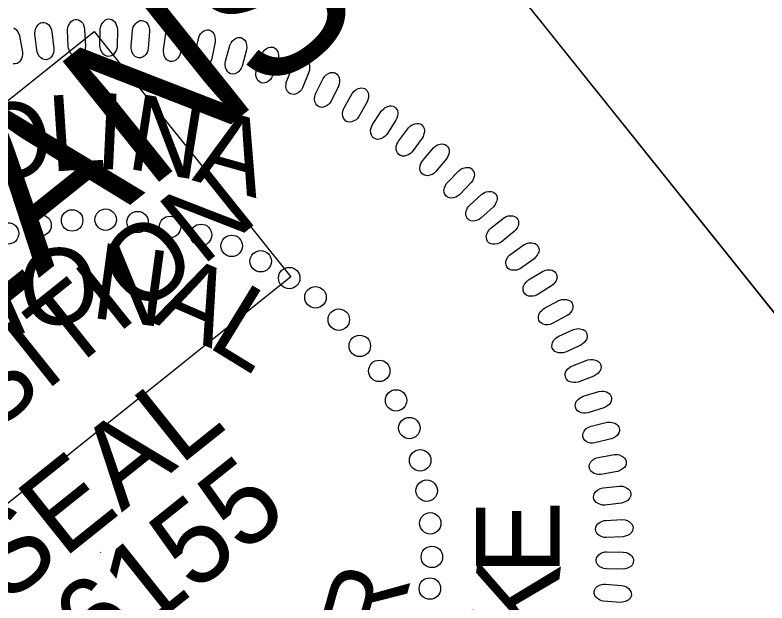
# Model space of a CAD drawing. Extents: x 473546 to 475544, y 505920 to 507827.
# Drawn here: x 474878.2 to 474934.4, y 507684.5 to 507728.4 of the extents above; entities that cross this region are included whole.
import ezdxf

# ---------------------------------------------------------------- set-up
doc = ezdxf.new("R2010")
doc.units = 0
for name, color, linetype in [('Sheet Plan CELL', 7, 'Continuous'), ('Sheet Profile Grid Minor CELL', 7, 'Continuous'), ('Sheet Sticker Incomplete CELL', 7, 'Continuous')]:
    doc.layers.add(name, color=color, linetype=linetype)

msp = doc.modelspace()

# ---------------------------------------------------------------- linework, layer by layer
at = {"layer": 'Sheet Plan CELL'}
for points in [[(474860.894, 507798.628), (473689.748, 506861.329), (474345.841, 506041.547), (475516.967, 506978.831)], [(474806.271, 507706.801), (474884.328, 507769.288), (474954.641, 507681.452), (474876.574, 507618.957)]]:
    msp.add_lwpolyline(points, close=True, dxfattribs=at)
at = {"layer": 'Sheet Profile Grid Minor CELL'}
msp.add_line((474884.563, 507688.269), (474884.592, 507688.232), dxfattribs=at)
for points in [[(474879.828, 507725.763), (474879.694, 507726.982), (474879.707, 507727.205), (474879.744, 507727.349), (474879.837, 507727.53), (474879.922, 507727.65), (474880.025, 507727.741), (474880.124, 507727.792), (474880.234, 507727.824), (474880.347, 507727.817), (474880.469, 507727.799), (474880.58, 507727.752), (474880.695, 507727.664), (474880.763, 507727.591), (474880.847, 507727.45), (474880.925, 507727.278), (474880.965, 507727.122), (474881.109, 507725.873), (474881.105, 507725.702), (474881.076, 507725.559), (474881.004, 507725.39), (474880.908, 507725.24), (474880.82, 507725.149), (474880.67, 507725.072), (474880.524, 507725.037), (474880.372, 507725.06), (474880.262, 507725.099), (474880.124, 507725.183), (474879.987, 507725.339), (474879.901, 507725.51), (474879.857, 507725.636)], [(474882.185, 507726.019), (474882.128, 507727.244), (474882.155, 507727.465), (474882.201, 507727.607), (474882.305, 507727.782), (474882.397, 507727.895), (474882.505, 507727.98), (474882.608, 507728.025), (474882.719, 507728.051), (474882.832, 507728.036), (474882.953, 507728.011), (474883.06, 507727.956), (474883.169, 507727.862), (474883.233, 507727.785), (474883.307, 507727.638), (474883.375, 507727.462), (474883.405, 507727.303), (474883.47, 507726.048), (474883.455, 507725.878), (474883.417, 507725.736), (474883.336, 507725.573), (474883.23, 507725.428), (474883.136, 507725.344), (474882.982, 507725.277), (474882.834, 507725.25), (474882.683, 507725.283), (474882.576, 507725.328), (474882.444, 507725.422), (474882.317, 507725.586), (474882.241, 507725.762), (474882.206, 507725.89)], [(474884.549, 507726.097), (474884.569, 507727.323), (474884.61, 507727.542), (474884.664, 507727.681), (474884.779, 507727.849), (474884.878, 507727.957), (474884.992, 507728.034), (474885.097, 507728.073), (474885.21, 507728.09), (474885.321, 507728.069), (474885.441, 507728.037), (474885.544, 507727.976), (474885.647, 507727.874), (474885.706, 507727.793), (474885.77, 507727.642), (474885.827, 507727.462), (474885.847, 507727.302), (474885.834, 507726.046), (474885.809, 507725.876), (474885.761, 507725.737), (474885.669, 507725.58), (474885.555, 507725.441), (474885.456, 507725.363), (474885.298, 507725.306), (474885.148, 507725.289), (474884.999, 507725.331), (474884.896, 507725.383), (474884.771, 507725.485), (474884.654, 507725.656), (474884.589, 507725.837), (474884.562, 507725.967)], [(474886.878, 507726.021), (474886.975, 507727.245), (474887.03, 507727.46), (474887.093, 507727.596), (474887.218, 507727.756), (474887.324, 507727.857), (474887.442, 507727.928), (474887.549, 507727.96), (474887.663, 507727.97), (474887.773, 507727.942), (474887.89, 507727.902), (474887.989, 507727.835), (474888.086, 507727.727), (474888.14, 507727.642), (474888.194, 507727.488), (474888.24, 507727.304), (474888.25, 507727.144), (474888.157, 507725.89), (474888.121, 507725.723), (474888.066, 507725.587), (474887.963, 507725.436), (474887.841, 507725.305), (474887.737, 507725.233), (474887.576, 507725.186), (474887.426, 507725.178), (474887.28, 507725.23), (474887.18, 507725.288), (474887.061, 507725.397), (474886.955, 507725.576), (474886.902, 507725.76), (474886.883, 507725.891)], [(474889.298, 507725.79), (474889.472, 507727.004), (474889.54, 507727.215), (474889.612, 507727.347), (474889.746, 507727.498), (474889.858, 507727.593), (474889.98, 507727.656), (474890.09, 507727.681), (474890.204, 507727.685), (474890.312, 507727.649), (474890.426, 507727.603), (474890.521, 507727.529), (474890.611, 507727.415), (474890.658, 507727.327), (474890.704, 507727.17), (474890.738, 507726.984), (474890.738, 507726.823), (474890.566, 507725.578), (474890.52, 507725.413), (474890.456, 507725.281), (474890.345, 507725.136), (474890.214, 507725.014), (474890.106, 507724.948), (474889.943, 507724.911), (474889.791, 507724.913), (474889.649, 507724.973), (474889.553, 507725.038), (474889.441, 507725.154), (474889.347, 507725.339), (474889.306, 507725.527), (474889.295, 507725.659)], [(474891.648, 507725.433), (474891.897, 507726.634), (474891.979, 507726.842), (474892.059, 507726.968), (474892.203, 507727.111), (474892.321, 507727.199), (474892.446, 507727.254), (474892.557, 507727.271), (474892.671, 507727.269), (474892.777, 507727.226), (474892.888, 507727.172), (474892.978, 507727.092), (474893.06, 507726.973), (474893.102, 507726.883), (474893.138, 507726.722), (474893.159, 507726.535), (474893.149, 507726.374), (474892.9, 507725.142), (474892.844, 507724.981), (474892.772, 507724.853), (474892.651, 507724.716), (474892.513, 507724.601), (474892.402, 507724.543), (474892.236, 507724.516), (474892.085, 507724.528), (474891.948, 507724.597), (474891.855, 507724.667), (474891.751, 507724.79), (474891.668, 507724.981), (474891.639, 507725.171), (474891.636, 507725.303)], [(474893.926, 507724.923), (474894.252, 507726.106), (474894.346, 507726.307), (474894.433, 507726.428), (474894.586, 507726.563), (474894.709, 507726.642), (474894.838, 507726.689), (474894.949, 507726.7), (474895.063, 507726.69), (474895.166, 507726.641), (474895.273, 507726.58), (474895.358, 507726.495), (474895.432, 507726.371), (474895.469, 507726.278), (474895.494, 507726.116), (474895.505, 507725.927), (474895.484, 507725.768), (474895.159, 507724.554), (474895.092, 507724.397), (474895.012, 507724.273), (474894.883, 507724.144), (474894.738, 507724.038), (474894.623, 507723.987), (474894.456, 507723.971), (474894.306, 507723.991), (474894.173, 507724.069), (474894.086, 507724.145), (474893.989, 507724.275), (474893.919, 507724.47), (474893.901, 507724.661), (474893.907, 507724.794)], [(474896.236, 507724.279), (474896.634, 507725.439), (474896.741, 507725.635), (474896.836, 507725.75), (474896.997, 507725.874), (474897.125, 507725.946), (474897.256, 507725.985), (474897.368, 507725.989), (474897.481, 507725.971), (474897.58, 507725.916), (474897.684, 507725.848), (474897.763, 507725.758), (474897.83, 507725.629), (474897.861, 507725.535), (474897.876, 507725.371), (474897.874, 507725.182), (474897.843, 507725.024), (474897.443, 507723.833), (474897.366, 507723.68), (474897.278, 507723.563), (474897.142, 507723.441), (474896.99, 507723.345), (474896.872, 507723.301), (474896.705, 507723.295), (474896.557, 507723.325), (474896.429, 507723.411), (474896.346, 507723.493), (474896.257, 507723.629), (474896.199, 507723.827), (474896.194, 507724.019), (474896.208, 507724.152)], [(474898.502, 507723.466), (474898.972, 507724.599), (474899.091, 507724.787), (474899.192, 507724.896), (474899.36, 507725.01), (474899.492, 507725.074), (474899.627, 507725.105), (474899.739, 507725.101), (474899.85, 507725.077), (474899.946, 507725.015), (474900.045, 507724.942), (474900.119, 507724.847), (474900.177, 507724.714), (474900.202, 507724.618), (474900.206, 507724.454), (474900.193, 507724.265), (474900.152, 507724.109), (474899.677, 507722.946), (474899.592, 507722.798), (474899.496, 507722.686), (474899.352, 507722.573), (474899.196, 507722.487), (474899.075, 507722.45), (474898.907, 507722.455), (474898.762, 507722.494), (474898.639, 507722.588), (474898.561, 507722.675), (474898.482, 507722.816), (474898.437, 507723.018), (474898.444, 507723.21), (474898.466, 507723.341)], [(474900.668, 507722.532), (474901.208, 507723.633), (474901.338, 507723.813), (474901.446, 507723.916), (474901.622, 507724.019), (474901.758, 507724.074), (474901.894, 507724.097), (474902.005, 507724.086), (474902.115, 507724.055), (474902.207, 507723.987), (474902.301, 507723.907), (474902.368, 507723.808), (474902.418, 507723.672), (474902.437, 507723.574), (474902.431, 507723.41), (474902.405, 507723.223), (474902.355, 507723.07), (474901.808, 507721.938), (474901.713, 507721.796), (474901.612, 507721.69), (474901.461, 507721.587), (474901.299, 507721.511), (474901.177, 507721.482), (474901.009, 507721.498), (474900.866, 507721.546), (474900.75, 507721.647), (474900.678, 507721.738), (474900.607, 507721.884), (474900.575, 507722.089), (474900.593, 507722.28), (474900.624, 507722.409)], [(474902.783, 507721.456), (474903.391, 507722.522), (474903.533, 507722.693), (474903.647, 507722.789), (474903.828, 507722.881), (474903.968, 507722.927), (474904.105, 507722.941), (474904.215, 507722.924), (474904.323, 507722.885), (474904.41, 507722.812), (474904.499, 507722.727), (474904.56, 507722.624), (474904.601, 507722.484), (474904.614, 507722.386), (474904.598, 507722.222), (474904.561, 507722.037), (474904.501, 507721.888), (474903.884, 507720.793), (474903.781, 507720.657), (474903.672, 507720.558), (474903.515, 507720.464), (474903.349, 507720.398), (474903.224, 507720.377), (474903.058, 507720.403), (474902.919, 507720.46), (474902.809, 507720.569), (474902.743, 507720.664), (474902.682, 507720.813), (474902.663, 507721.02), (474902.693, 507721.209), (474902.732, 507721.337)], [(474904.911, 507720.196), (474905.586, 507721.221), (474905.738, 507721.383), (474905.858, 507721.472), (474906.045, 507721.551), (474906.186, 507721.59), (474906.324, 507721.595), (474906.433, 507721.571), (474906.538, 507721.525), (474906.62, 507721.447), (474906.704, 507721.356), (474906.758, 507721.249), (474906.791, 507721.108), (474906.798, 507721.009), (474906.771, 507720.846), (474906.723, 507720.664), (474906.654, 507720.518), (474905.969, 507719.464), (474905.857, 507719.335), (474905.742, 507719.243), (474905.58, 507719.159), (474905.41, 507719.104), (474905.285, 507719.091), (474905.12, 507719.127), (474904.985, 507719.193), (474904.882, 507719.308), (474904.822, 507719.407), (474904.77, 507719.561), (474904.764, 507719.767), (474904.806, 507719.955), (474904.852, 507720.08)], [(474906.851, 507718.965), (474907.588, 507719.945), (474907.749, 507720.097), (474907.875, 507720.178), (474908.067, 507720.247), (474908.211, 507720.276), (474908.348, 507720.272), (474908.456, 507720.241), (474908.557, 507720.189), (474908.635, 507720.106), (474908.713, 507720.01), (474908.76, 507719.9), (474908.784, 507719.757), (474908.784, 507719.657), (474908.747, 507719.497), (474908.687, 507719.317), (474908.61, 507719.177), (474907.86, 507718.168), (474907.74, 507718.046), (474907.62, 507717.961), (474907.453, 507717.888), (474907.28, 507717.843), (474907.154, 507717.838), (474906.993, 507717.885), (474906.861, 507717.959), (474906.766, 507718.081), (474906.712, 507718.183), (474906.67, 507718.339), (474906.676, 507718.546), (474906.731, 507718.73), (474906.785, 507718.852)], [(474908.657, 507717.523), (474909.455, 507718.455), (474909.626, 507718.597), (474909.756, 507718.67), (474909.952, 507718.726), (474910.096, 507718.746), (474910.234, 507718.734), (474910.339, 507718.696), (474910.438, 507718.638), (474910.509, 507718.55), (474910.581, 507718.449), (474910.621, 507718.336), (474910.636, 507718.193), (474910.63, 507718.093), (474910.584, 507717.935), (474910.512, 507717.76), (474910.426, 507717.624), (474909.615, 507716.664), (474909.487, 507716.55), (474909.362, 507716.474), (474909.191, 507716.411), (474909.015, 507716.378), (474908.889, 507716.38), (474908.73, 507716.436), (474908.604, 507716.519), (474908.517, 507716.646), (474908.469, 507716.752), (474908.437, 507716.91), (474908.457, 507717.117), (474908.523, 507717.298), (474908.584, 507717.415)], [(474910.492, 507715.868), (474911.347, 507716.747), (474911.526, 507716.879), (474911.661, 507716.943), (474911.86, 507716.987), (474912.006, 507716.998), (474912.142, 507716.977), (474912.245, 507716.933), (474912.338, 507716.869), (474912.405, 507716.776), (474912.47, 507716.671), (474912.504, 507716.556), (474912.509, 507716.411), (474912.497, 507716.313), (474912.441, 507716.158), (474912.359, 507715.987), (474912.264, 507715.857), (474911.394, 507714.95), (474911.259, 507714.845), (474911.13, 507714.776), (474910.955, 507714.724), (474910.777, 507714.702), (474910.652, 507714.712), (474910.497, 507714.778), (474910.376, 507714.869), (474910.297, 507715.001), (474910.257, 507715.11), (474910.235, 507715.27), (474910.267, 507715.475), (474910.344, 507715.65), (474910.413, 507715.764)], [(474912.16, 507714.174), (474913.068, 507714.998), (474913.256, 507715.117), (474913.394, 507715.173), (474913.595, 507715.204), (474913.741, 507715.206), (474913.876, 507715.176), (474913.975, 507715.126), (474914.066, 507715.056), (474914.126, 507714.96), (474914.185, 507714.851), (474914.211, 507714.734), (474914.207, 507714.589), (474914.188, 507714.491), (474914.123, 507714.341), (474914.03, 507714.175), (474913.928, 507714.052), (474913.002, 507713.201), (474912.862, 507713.104), (474912.728, 507713.044), (474912.55, 507713.003), (474912.371, 507712.992), (474912.247, 507713.01), (474912.097, 507713.086), (474911.981, 507713.183), (474911.911, 507713.321), (474911.877, 507713.432), (474911.865, 507713.593), (474911.91, 507713.795), (474911.998, 507713.966), (474912.074, 507714.075)], [(474913.732, 507712.447), (474914.691, 507713.214), (474914.885, 507713.321), (474915.027, 507713.368), (474915.23, 507713.386), (474915.376, 507713.379), (474915.508, 507713.341), (474915.604, 507713.284), (474915.69, 507713.209), (474915.745, 507713.109), (474915.796, 507712.997), (474915.814, 507712.878), (474915.802, 507712.734), (474915.777, 507712.637), (474915.702, 507712.491), (474915.599, 507712.332), (474915.489, 507712.215), (474914.512, 507711.424), (474914.366, 507711.336), (474914.228, 507711.284), (474914.048, 507711.254), (474913.869, 507711.255), (474913.746, 507711.281), (474913.601, 507711.366), (474913.492, 507711.47), (474913.43, 507711.612), (474913.404, 507711.725), (474913.402, 507711.886), (474913.46, 507712.086), (474913.558, 507712.25), (474913.64, 507712.355)], [(474915.232, 507710.521), (474916.236, 507711.226), (474916.436, 507711.32), (474916.581, 507711.358), (474916.785, 507711.364), (474916.931, 507711.348), (474917.06, 507711.302), (474917.152, 507711.239), (474917.233, 507711.158), (474917.281, 507711.055), (474917.325, 507710.94), (474917.337, 507710.82), (474917.315, 507710.677), (474917.284, 507710.583), (474917.2, 507710.441), (474917.087, 507710.289), (474916.97, 507710.179), (474915.945, 507709.451), (474915.794, 507709.373), (474915.653, 507709.329), (474915.472, 507709.311), (474915.293, 507709.323), (474915.172, 507709.356), (474915.032, 507709.45), (474914.93, 507709.562), (474914.877, 507709.707), (474914.858, 507709.821), (474914.867, 507709.982), (474914.937, 507710.177), (474915.045, 507710.336), (474915.134, 507710.434)], [(474916.563, 507708.59), (474917.61, 507709.23), (474917.817, 507709.313), (474917.963, 507709.341), (474918.167, 507709.335), (474918.311, 507709.309), (474918.437, 507709.254), (474918.526, 507709.186), (474918.601, 507709.1), (474918.643, 507708.995), (474918.68, 507708.877), (474918.683, 507708.757), (474918.653, 507708.615), (474918.616, 507708.523), (474918.523, 507708.387), (474918.402, 507708.243), (474918.277, 507708.14), (474917.209, 507707.478), (474917.052, 507707.408), (474916.91, 507707.374), (474916.727, 507707.367), (474916.55, 507707.39), (474916.431, 507707.431), (474916.298, 507707.534), (474916.203, 507707.651), (474916.159, 507707.8), (474916.147, 507707.915), (474916.165, 507708.075), (474916.248, 507708.265), (474916.366, 507708.417), (474916.461, 507708.51)], [(474917.745, 507706.479), (474918.83, 507707.051), (474919.041, 507707.121), (474919.189, 507707.141), (474919.392, 507707.12), (474919.534, 507707.085), (474919.657, 507707.024), (474919.741, 507706.95), (474919.811, 507706.86), (474919.846, 507706.752), (474919.875, 507706.632), (474919.871, 507706.511), (474919.831, 507706.372), (474919.789, 507706.282), (474919.689, 507706.153), (474919.558, 507706.016), (474919.428, 507705.922), (474918.32, 507705.328), (474918.159, 507705.268), (474918.015, 507705.243), (474917.832, 507705.248), (474917.656, 507705.282), (474917.54, 507705.33), (474917.414, 507705.441), (474917.326, 507705.564), (474917.292, 507705.715), (474917.287, 507705.831), (474917.315, 507705.989), (474917.41, 507706.174), (474917.537, 507706.318), (474917.638, 507706.404)], [(474918.806, 507704.383), (474919.925, 507704.887), (474920.14, 507704.942), (474920.289, 507704.953), (474920.49, 507704.92), (474920.629, 507704.876), (474920.749, 507704.806), (474920.827, 507704.728), (474920.892, 507704.633), (474920.92, 507704.524), (474920.942, 507704.402), (474920.93, 507704.282), (474920.882, 507704.146), (474920.834, 507704.058), (474920.725, 507703.935), (474920.586, 507703.807), (474920.45, 507703.721), (474919.307, 507703.198), (474919.143, 507703.149), (474918.997, 507703.133), (474918.816, 507703.149), (474918.642, 507703.194), (474918.53, 507703.249), (474918.41, 507703.368), (474918.331, 507703.496), (474918.306, 507703.649), (474918.308, 507703.765), (474918.347, 507703.922), (474918.452, 507704.1), (474918.589, 507704.236), (474918.694, 507704.315)], [(474919.838, 507702.177), (474920.986, 507702.61), (474921.205, 507702.652), (474921.354, 507702.653), (474921.552, 507702.608), (474921.689, 507702.556), (474921.803, 507702.478), (474921.877, 507702.395), (474921.935, 507702.297), (474921.956, 507702.185), (474921.97, 507702.062), (474921.952, 507701.944), (474921.895, 507701.81), (474921.841, 507701.726), (474921.725, 507701.611), (474921.578, 507701.491), (474921.437, 507701.414), (474920.264, 507700.964), (474920.097, 507700.925), (474919.95, 507700.918), (474919.77, 507700.945), (474919.599, 507701.001), (474919.491, 507701.064), (474919.379, 507701.189), (474919.308, 507701.323), (474919.293, 507701.476), (474919.302, 507701.592), (474919.35, 507701.746), (474919.467, 507701.918), (474919.612, 507702.044), (474919.722, 507702.117)], [(474920.636, 507699.898), (474921.809, 507700.258), (474922.03, 507700.286), (474922.178, 507700.278), (474922.374, 507700.22), (474922.507, 507700.159), (474922.616, 507700.075), (474922.684, 507699.987), (474922.737, 507699.885), (474922.751, 507699.773), (474922.757, 507699.65), (474922.731, 507699.532), (474922.666, 507699.403), (474922.607, 507699.322), (474922.484, 507699.214), (474922.33, 507699.104), (474922.184, 507699.036), (474920.984, 507698.66), (474920.816, 507698.632), (474920.669, 507698.634), (474920.49, 507698.673), (474920.324, 507698.739), (474920.219, 507698.808), (474920.116, 507698.941), (474920.053, 507699.078), (474920.047, 507699.233), (474920.065, 507699.348), (474920.122, 507699.498), (474920.25, 507699.662), (474920.402, 507699.779), (474920.517, 507699.846)], [(474921.239, 507697.669), (474922.432, 507697.954), (474922.654, 507697.968), (474922.802, 507697.951), (474922.993, 507697.881), (474923.123, 507697.812), (474923.226, 507697.721), (474923.289, 507697.629), (474923.335, 507697.524), (474923.341, 507697.411), (474923.34, 507697.287), (474923.307, 507697.172), (474923.234, 507697.047), (474923.17, 507696.97), (474923.04, 507696.87), (474922.88, 507696.77), (474922.73, 507696.711), (474921.509, 507696.411), (474921.339, 507696.393), (474921.193, 507696.405), (474921.017, 507696.455), (474920.855, 507696.532), (474920.755, 507696.607), (474920.66, 507696.746), (474920.606, 507696.887), (474920.61, 507697.041), (474920.634, 507697.155), (474920.701, 507697.302), (474920.839, 507697.458), (474920.998, 507697.565), (474921.116, 507697.624)], [(474921.762, 507695.336), (474922.971, 507695.546), (474923.193, 507695.547), (474923.34, 507695.52), (474923.527, 507695.438), (474923.652, 507695.361), (474923.749, 507695.264), (474923.806, 507695.168), (474923.845, 507695.061), (474923.845, 507694.947), (474923.835, 507694.824), (474923.795, 507694.712), (474923.714, 507694.591), (474923.646, 507694.518), (474923.51, 507694.426), (474923.343, 507694.337), (474923.19, 507694.287), (474921.953, 507694.064), (474921.782, 507694.057), (474921.637, 507694.078), (474921.465, 507694.139), (474921.308, 507694.226), (474921.213, 507694.308), (474921.127, 507694.452), (474921.081, 507694.596), (474921.095, 507694.75), (474921.127, 507694.862), (474921.203, 507695.004), (474921.349, 507695.151), (474921.515, 507695.248), (474921.637, 507695.3)], [(474922.132, 507693.055), (474923.352, 507693.189), (474923.574, 507693.175), (474923.718, 507693.139), (474923.899, 507693.046), (474924.019, 507692.962), (474924.11, 507692.858), (474924.161, 507692.759), (474924.193, 507692.649), (474924.185, 507692.536), (474924.169, 507692.414), (474924.121, 507692.303), (474924.033, 507692.189), (474923.96, 507692.12), (474923.818, 507692.037), (474923.647, 507691.958), (474923.491, 507691.918), (474922.242, 507691.774), (474922.071, 507691.778), (474921.927, 507691.808), (474921.76, 507691.879), (474921.608, 507691.975), (474921.519, 507692.063), (474921.442, 507692.213), (474921.406, 507692.36), (474921.429, 507692.512), (474921.467, 507692.622), (474921.552, 507692.759), (474921.708, 507692.896), (474921.88, 507692.983), (474922.005, 507693.027)], [(474922.329, 507690.632), (474923.554, 507690.688), (474923.775, 507690.661), (474923.917, 507690.616), (474924.092, 507690.511), (474924.206, 507690.419), (474924.291, 507690.31), (474924.336, 507690.208), (474924.361, 507690.097), (474924.346, 507689.984), (474924.322, 507689.863), (474924.267, 507689.756), (474924.172, 507689.647), (474924.095, 507689.583), (474923.949, 507689.509), (474923.772, 507689.441), (474923.614, 507689.411), (474922.359, 507689.345), (474922.189, 507689.36), (474922.047, 507689.399), (474921.883, 507689.481), (474921.739, 507689.586), (474921.654, 507689.68), (474921.587, 507689.834), (474921.561, 507689.982), (474921.593, 507690.133), (474921.638, 507690.24), (474921.732, 507690.372), (474921.896, 507690.499), (474922.073, 507690.575), (474922.2, 507690.61)], [(474922.408, 507688.285), (474923.634, 507688.265), (474923.852, 507688.224), (474923.991, 507688.17), (474924.159, 507688.055), (474924.267, 507687.956), (474924.345, 507687.842), (474924.383, 507687.737), (474924.401, 507687.624), (474924.379, 507687.513), (474924.347, 507687.393), (474924.286, 507687.29), (474924.184, 507687.187), (474924.104, 507687.129), (474923.953, 507687.064), (474923.773, 507687.007), (474923.613, 507686.987), (474922.356, 507687), (474922.187, 507687.026), (474922.048, 507687.073), (474921.89, 507687.165), (474921.752, 507687.279), (474921.674, 507687.379), (474921.617, 507687.536), (474921.6, 507687.686), (474921.642, 507687.835), (474921.694, 507687.939), (474921.795, 507688.064), (474921.966, 507688.181), (474922.147, 507688.245), (474922.277, 507688.273)], [(474922.294, 507685.875), (474923.517, 507685.778), (474923.733, 507685.724), (474923.868, 507685.66), (474924.028, 507685.535), (474924.13, 507685.429), (474924.201, 507685.311), (474924.232, 507685.204), (474924.242, 507685.09), (474924.214, 507684.98), (474924.174, 507684.863), (474924.107, 507684.764), (474923.999, 507684.667), (474923.915, 507684.614), (474923.76, 507684.559), (474923.577, 507684.513), (474923.416, 507684.503), (474922.163, 507684.596), (474921.995, 507684.632), (474921.859, 507684.688), (474921.708, 507684.79), (474921.578, 507684.912), (474921.506, 507685.016), (474921.458, 507685.177), (474921.451, 507685.328), (474921.502, 507685.473), (474921.561, 507685.574), (474921.67, 507685.693), (474921.848, 507685.798), (474922.033, 507685.851), (474922.164, 507685.871)]]:
    msp.add_lwpolyline(points, close=True, dxfattribs=at)
msp.add_lwpolyline([(474878.106, 507727.434), (474878.227, 507727.354), (474878.299, 507727.285), (474878.391, 507727.15), (474878.48, 507726.983), (474878.53, 507726.83), (474878.752, 507725.593), (474878.759, 507725.422), (474878.739, 507725.277), (474878.678, 507725.104), (474878.591, 507724.947), (474878.51, 507724.852), (474878.365, 507724.766), (474878.221, 507724.721), (474878.067, 507724.734)], dxfattribs=at)
for centre in [(474882.471, 507713.031), (474884.971, 507713.093), (474887.359, 507712.911), (474880.108, 507712.672), (474889.785, 507712.556), (474877.688, 507712.063), (474892.098, 507711.958), (474894.387, 507711.136), (474896.552, 507709.987), (474898.679, 507708.73), (474900.645, 507707.292), (474902.386, 507705.624), (474903.954, 507703.664), (474905.407, 507701.8), (474906.664, 507699.591), (474907.653, 507697.526), (474908.462, 507695.112), (474908.948, 507692.848), (474909.215, 507690.41), (474909.334, 507687.903), (474909.185, 507685.539)]:
    msp.add_circle(centre, 0.801, dxfattribs=at)
at = {"layer": 'Sheet Sticker Incomplete CELL'}
msp.add_lwpolyline([(474784.034, 507616.957), (474769.35, 507635.305), (474884.119, 507727.158), (474898.803, 507708.81)], close=True, dxfattribs=at)

# ---------------------------------------------------------------- texts
at = {"layer": 'Sheet Profile Grid Minor CELL'}
for s, height, rotation, p in [('L', 5.669, 3.8121, (474880.855, 507716.672)), ('I', 5.669, 357.3228, (474884.116, 507716.908)), ('N', 5.669, 350.8334, (474886.413, 507716.927)), ('O', 5.669, 10.3015, (474875.579, 507715.691)), ('A', 5.669, 344.344, (474891.367, 507716.05)), ('O', 5.669, 8.2011, (474878.952, 507704.893)), ('N', 5.669, 352.3215, (474883.758, 507705.788)), ('I', 5.669, 24.0807, (474877.671, 507704.087)), ('A', 5.669, 336.4419, (474888.289, 507705.468)), ('L', 5.669, 328.5021, (474892.443, 507703.676)), ('SEAL', 6.2363, 38.6526, (474877.476, 507684.253)), ('46155', 6.2363, 38.6526, (474880.691, 507676.479)), ('E', 6.236, 89.9395, (474918.869, 507686.528)), ('K', 6.236, 83.0938, (474918.319, 507681.766)), ('R', 5.669, 74.3348, (474906.337, 507681.015))]:
    msp.add_text(s, height=height, rotation=rotation, dxfattribs=at).set_placement(p)
at = {"layer": 'Sheet Sticker Incomplete CELL'}
for s, height, p in [('INCOMPLETE PLANS', 11.52, (474783.711, 507631.684)), ('DO NOT USE FOR R/W ACQUISITION', 5.76, (474790.591, 507628.289))]:
    msp.add_text(s, height=height, rotation=38.6712, dxfattribs=at).set_placement(p)

doc.saveas('drawing.dxf')
